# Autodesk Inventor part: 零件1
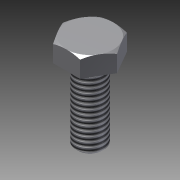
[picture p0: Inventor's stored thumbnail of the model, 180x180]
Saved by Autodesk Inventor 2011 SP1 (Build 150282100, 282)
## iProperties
Created: 2013-12
Part Number: 零件1
Document SubType Name: Modeling
Designer: Administrator
Density: 1 g/cm^3
Author: Administrator
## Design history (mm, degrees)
sketch "草图1"
  geometry: L1 (5.774, 0)-(2.887, -5); L2 (2.887, -5)-(-2.887, -5); L3 (-2.887, -5)-(-5.774, 0); L4 (-5.774, 0)-(-2.887, 5); L5 (-2.887, 5)-(2.887, 5); L6 (2.887, 5)-(5.774, 0); 2 further points
  constraints: 12 end point, 1 coincident, 13 other
  dimensions: "d0" = 10 distance between parallel lines of L2 L5
extrude "拉伸1" new body sketch "草图1" distance "d1" = 4; taper "d2" = 0 deg
sketch "草图2"
  geometry: C1 r 3 at (0, 0); 1 further point
  constraints: 1 centre point, 1 coincident
  dimensions: "d3" = 6 diameter of C1
extrude "拉伸2" join sketch "草图2" distance "d4" = 16; taper "d5" = 0 deg
feature "螺纹1" dims "d6" = 10, "d7" = 0
chamfer "倒角1" distance "d8" = 0.5; stored, may be unused: second distance "d9" = 2, angle "d10" = 45 deg
sketch "草图3"
  geometry: L1 (2.887, -5)-(-2.887, -5) reference; L2 (5.774, 0)-(2.887, -5) reference; L3 (2.887, 5)-(5.774, 0) reference; L4 (-2.887, 5)-(2.887, 5) reference; L5 (-5.774, 0)-(-2.887, 5) reference; L6 (-2.887, -5)-(-5.774, 0) reference; C1 r 5 at (0, 0); 1 further point
  constraints: 1 centre point, 1 coincident, 1 tangent
sketch "草图4"
  geometry: L1 (-2.887, 4)-(2.887, 4) reference; L2 (-5.774, 4)-(-2.887, 4) reference; L3 (-2.887, 4)-(-5.774, 4) reference; L4 (2.887, 4)-(-2.887, 4) reference; L5 (5.774, 4)-(2.887, 4) reference; L6 (2.887, 4)-(5.774, 4) reference; L7 (5, 4)-(-5, 4) reference; L8 (-5, 4)-(-6.065, 3.385); L9 (-5, 4)-(-5.774, 4); L10 (-5.774, 3.553)-(-5.774, 4); L11 (0, -20)-(0, 8) reference; 1 further point
  constraints: 6 end point, 1 collinear, 1 perpendicular, 1 point on line
  dimensions: "d11" = 30 deg angle of L2 L8
revolve "旋转1" sketch "草图4" stored, may be unused: angle "d12" = 90 deg
sketch "草图5"
  geometry: A1 r 5 centre (0, 0) between (4.33, 2.5) and (0, 5) reference; A2 r 5 centre (0, 0) between (0, 5) and (-4.33, 2.5) reference; A3 r 5 centre (0, 0) between (-4.33, 2.5) and (-4.33, -2.5) reference; A4 r 5 centre (0, 0) between (-4.33, -2.5) and (0, -5) reference; A5 r 5 centre (0, 0) between (0, -5) and (4.33, -2.5) reference; A6 r 5 centre (0, 0) between (4.33, -2.5) and (4.33, 2.5) reference
sketch "草图6"
  geometry: A1 r 5 centre (0, 0) between (4.33, 2.5) and (0, 5) reference; A2 r 5 centre (0, 0) between (0, 5) and (-4.33, 2.5) reference; A3 r 5 centre (0, 0) between (-4.33, 2.5) and (-4.33, -2.5) reference; A4 r 5 centre (0, 0) between (-4.33, -2.5) and (0, -5) reference; A5 r 5 centre (0, 0) between (0, -5) and (4.33, -2.5) reference; A6 r 5 centre (0, 0) between (4.33, -2.5) and (4.33, 2.5) reference
node "实体1"
node "投影回路1"
